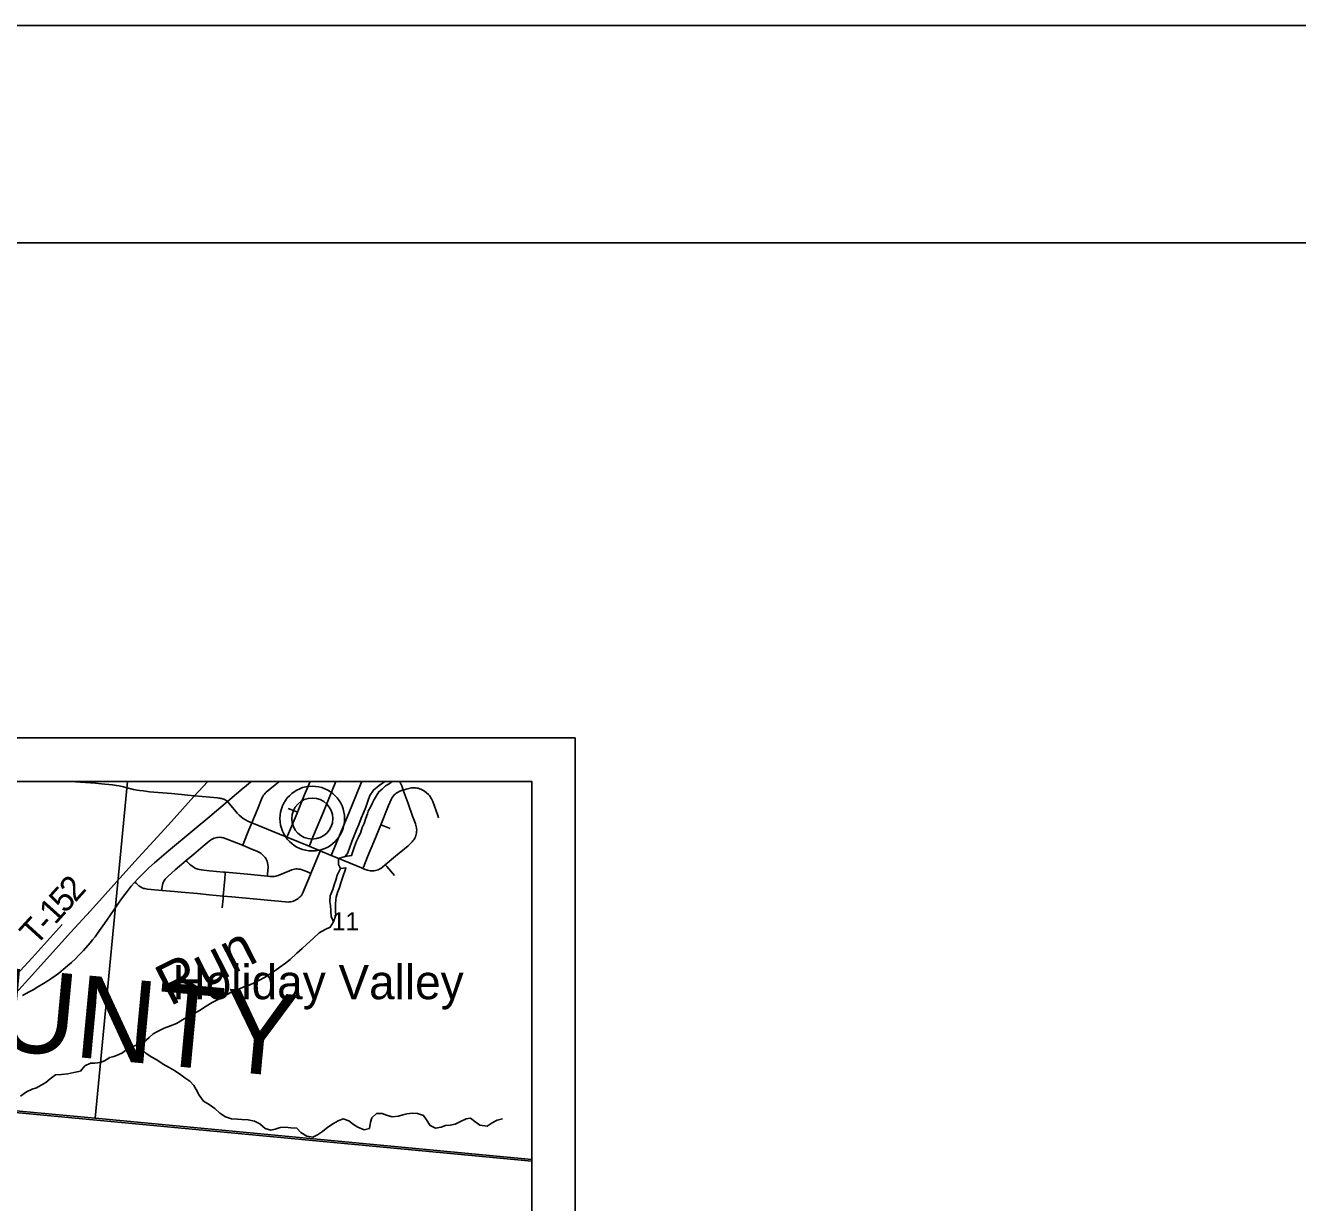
# Model space of a CAD drawing. Extents: x 0 to 34, y 0 to 22.
# Drawn here: x 28.153 to 31.076, y 19.293 to 22 of the extents above; entities that cross this region are included whole.
import ezdxf

# ---------------------------------------------------------------- set-up
doc = ezdxf.new("R2010")
doc.units = 0
for name, color, linetype in [('GM_X_County_Road', 7, 'Continuous'), ('GM_X_County_Text', 7, 'Continuous'), ('GM_X_Minor_Lake', 7, 'Continuous'), ('GM_X_Minor_River', 7, 'Continuous'), ('GM_X_Minor_River_Text', 7, 'Continuous'), ('GM_X_Rail_Line', 7, 'Continuous'), ('GM_X_Section_Text', 7, 'Continuous'), ('GM_X_Township_Road', 7, 'Continuous'), ('GM_X_Township_Road_Text', 7, 'Continuous'), ('GM_X_Unincorporated', 7, 'Continuous'), ('GM_X_Unincorporated_Location', 7, 'Continuous'), ('GM_X_Unincorporated_Text', 7, 'Continuous'), ('SH_Border', 7, 'Continuous'), ('SH_Cut_Line', 7, 'Continuous'), ('SH_Data', 7, 'Continuous')]:
    doc.layers.add(name, color=color, linetype=linetype)

msp = doc.modelspace()

# ---------------------------------------------------------------- linework, layer by layer
at = {"layer": 'GM_X_County_Road'}
for points in [[(28.3874, 20.2618), (27.4198, 20.2618), (27.3522, 19.5759), (28.313, 19.4872)], [(29.3164, 19.3923), (29.3164, 20.2618), (28.3874, 20.2618), (28.313, 19.4872)]]:
    msp.add_lwpolyline(points, close=True, dxfattribs=at)
for points in [[(28.2565, 20.2618), (28.3138, 20.2574), (28.3276, 20.2563), (28.3353, 20.2556), (28.3448, 20.2546), (28.353, 20.2536), (28.3579, 20.2529), (28.3621, 20.2523), (28.3681, 20.2512), (28.3786, 20.2491), (28.3836, 20.248), (28.4014, 20.2434), (28.4057, 20.2425), (28.4091, 20.2419), (28.4154, 20.2408), (28.424, 20.2397), (28.4381, 20.2381), (28.4889, 20.2336), (28.5415, 20.2285), (28.5941, 20.2237), (28.5977, 20.2233), (28.5998, 20.223), (28.602, 20.2227), (28.6032, 20.2224), (28.6042, 20.2222), (28.6052, 20.2219), (28.6069, 20.2213), (28.6088, 20.2206), (28.6116, 20.2195), (28.6141, 20.2181), (28.617, 20.2155)], [(28.617, 20.2155), (28.6535, 20.246), (28.66, 20.2516), (28.6716, 20.2618)], [(28.4041, 20.03), (28.4108, 20.0371), (28.4196, 20.0465), (28.4277, 20.0545), (28.4367, 20.0628), (28.4494, 20.0741), (28.4819, 20.102), (28.5406, 20.151), (28.5764, 20.1808), (28.617, 20.2155)], [(28.1462, 19.7698), (28.1612, 19.7776), (28.1703, 19.7826), (28.1817, 19.7892), (28.1945, 19.797), (28.2044, 19.8032), (28.2138, 19.8095), (28.2287, 19.8203), (28.2399, 19.8292), (28.2497, 19.8374), (28.2585, 19.8453), (28.2681, 19.8541), (28.2757, 19.8618), (28.2863, 19.8728), (28.3019, 19.8906), (28.3073, 19.8973), (28.3129, 19.9047), (28.3177, 19.9111), (28.3401, 19.943), (28.374, 19.9919), (28.3887, 20.0118), (28.396, 20.0208), (28.4026, 20.0284), (28.4041, 20.03)]]:
    msp.add_lwpolyline(points, dxfattribs=at)
at = {"layer": 'GM_X_Minor_Lake'}
for points in [[(28.8875, 20.0893), (28.9025, 20.091), (28.9053, 20.1009), (28.9088, 20.1118), (28.9135, 20.1242), (28.9181, 20.1333), (28.924, 20.1453), (28.9271, 20.1559), (28.9314, 20.1653), (28.9353, 20.177), (28.9388, 20.1872), (28.9404, 20.1933), (28.9458, 20.2023), (28.9505, 20.2121), (28.954, 20.22), (28.9586, 20.2279), (28.9652, 20.238), (28.9724, 20.2436), (28.9805, 20.2515), (28.9888, 20.2563), (28.996, 20.2618)], [(28.8875, 20.0893), (28.8939, 20.0972), (28.8982, 20.1104), (28.9033, 20.1236), (28.9088, 20.1387), (28.9138, 20.1504), (28.9193, 20.1628), (28.9243, 20.1768), (28.9302, 20.1892), (28.9353, 20.2028), (28.94, 20.2164), (28.9447, 20.2292), (28.9527, 20.2416), (28.9657, 20.2524), (28.9791, 20.2617), (28.9792, 20.2618)], [(28.8773, 20.0616), (28.8694, 20.046), (28.8659, 20.0343), (28.8624, 20.0241), (28.8592, 20.0131), (28.853, 19.9988), (28.8524, 19.9859), (28.8542, 19.9764), (28.8544, 19.9643), (28.8554, 19.951), (28.8609, 19.9388)], [(28.8609, 19.9388), (28.866, 19.9543), (28.8658, 19.9627), (28.8655, 19.9725), (28.8656, 19.9801), (28.8665, 19.9892), (28.8673, 19.9952), (28.8701, 20.0066), (28.8748, 20.0179), (28.8779, 20.0284), (28.8807, 20.0375), (28.8838, 20.0466), (28.8873, 20.0556), (28.8893, 20.0632), (28.8773, 20.0616)]]:
    msp.add_lwpolyline(points, dxfattribs=at)
at = {"layer": 'GM_X_Minor_River'}
for points in [[(28.3563, 19.6294), (28.3658, 19.633), (28.3757, 19.6375), (28.3883, 19.6472), (28.4016, 19.6531), (28.4122, 19.6571), (28.4247, 19.6619), (28.437, 19.6727), (28.4465, 19.6813), (28.4583, 19.6876), (28.472, 19.6943), (28.4864, 19.6998), (28.5001, 19.7049), (28.5142, 19.7135), (28.5241, 19.7194), (28.5408, 19.7283), (28.5526, 19.7353), (28.5682, 19.7446), (28.582, 19.7536), (28.5957, 19.7602), (28.6063, 19.7673), (28.6193, 19.7736), (28.6307, 19.7802), (28.6436, 19.7842), (28.6546, 19.789), (28.6671, 19.7934), (28.6782, 19.7986), (28.6896, 19.8038), (28.7025, 19.8108), (28.7132, 19.8179), (28.7261, 19.8261), (28.7376, 19.8343), (28.7505, 19.8439), (28.7612, 19.8525), (28.7765, 19.8664), (28.7891, 19.8776), (28.7991, 19.8869), (28.8147, 19.9011), (28.8277, 19.9135), (28.8414, 19.9209), (28.8536, 19.9268), (28.8609, 19.9388), (28.8554, 19.951), (28.8544, 19.9643), (28.8542, 19.9764), (28.8524, 19.9859), (28.853, 19.9988), (28.8592, 20.0131), (28.8624, 20.0241), (28.8659, 20.0343), (28.8694, 20.046), (28.8773, 20.0616), (28.872, 20.0706), (28.8722, 20.0846), (28.8875, 20.0893), (28.8939, 20.0972), (28.8982, 20.1104), (28.9033, 20.1236), (28.9088, 20.1387), (28.9138, 20.1504), (28.9193, 20.1628), (28.9243, 20.1768), (28.9302, 20.1892), (28.9353, 20.2028), (28.94, 20.2164), (28.9447, 20.2292), (28.9527, 20.2416), (28.9657, 20.2524), (28.9791, 20.2617), (28.9792, 20.2618)], [(28.4087, 19.6558), (28.4178, 19.6483), (28.4297, 19.6368), (28.4421, 19.6283), (28.4552, 19.6217), (28.4691, 19.6113), (28.4834, 19.6036), (28.4939, 19.5981), (28.507, 19.5893), (28.519, 19.5804), (28.531, 19.5723), (28.5399, 19.5627), (28.5455, 19.5532), (28.5525, 19.5402), (28.5622, 19.5264), (28.5753, 19.5187), (28.588, 19.5098), (28.5996, 19.4991), (28.6124, 19.4906), (28.6267, 19.4862), (28.6406, 19.4849), (28.6505, 19.484), (28.6644, 19.4835), (28.6791, 19.4807), (28.6915, 19.4745), (28.7039, 19.4633), (28.7171, 19.4597), (28.7265, 19.4619), (28.7383, 19.4659), (28.7508, 19.4665), (28.7629, 19.4652), (28.7768, 19.4643), (28.7858, 19.4547), (28.7997, 19.4458), (28.8132, 19.4438), (28.8243, 19.4493), (28.8353, 19.4564), (28.8479, 19.4668), (28.8612, 19.475), (28.8719, 19.481), (28.8829, 19.4857), (28.8961, 19.4814), (28.907, 19.4729), (28.9167, 19.4668), (28.931, 19.4609), (28.9435, 19.4638), (28.9456, 19.4778), (28.9487, 19.4883), (28.9598, 19.4984), (28.9727, 19.4979), (28.9828, 19.494), (28.9956, 19.4904), (29.0104, 19.4918), (29.0202, 19.495), (29.0297, 19.4976), (29.0415, 19.499), (29.0543, 19.4984), (29.0678, 19.4933), (29.0749, 19.4838), (29.0827, 19.4704), (29.0955, 19.4646), (29.108, 19.4663), (29.1186, 19.4703), (29.1288, 19.4713), (29.1402, 19.4735), (29.1531, 19.4794), (29.166, 19.486), (29.1759, 19.4874), (29.1856, 19.4797), (29.1972, 19.4709), (29.2138, 19.4692), (29.2256, 19.477), (29.2367, 19.4825), (29.2496, 19.4858)], [(28.1416, 19.538), (28.1557, 19.5481), (28.1683, 19.5544), (28.1781, 19.5573), (28.1892, 19.5636), (28.1998, 19.5691), (28.2101, 19.5781), (28.2223, 19.5867), (28.2356, 19.5876), (28.2507, 19.5894), (28.264, 19.5922), (28.2791, 19.5955), (28.2895, 19.6074), (28.3024, 19.6141), (28.3123, 19.614), (28.3244, 19.6154), (28.3346, 19.6194), (28.3468, 19.6268), (28.3563, 19.6294)]]:
    msp.add_lwpolyline(points, dxfattribs=at)
at = {"layer": 'GM_X_Rail_Line'}
msp.add_lwpolyline([(27.9011, 19.5213), (28.1, 19.7406), (28.1155, 19.7578), (28.16, 19.8071), (28.2576, 19.9148), (28.3022, 19.9642), (28.3365, 20.0019), (28.4044, 20.0773), (28.4814, 20.1618), (28.54, 20.2267), (28.5717, 20.2618)], dxfattribs=at)
at = {"layer": 'GM_X_Township_Road'}
for p, q in [((28.6732, 20.1667), (28.754, 20.1334)), ((28.805, 20.1125), (28.8305, 20.102)), ((28.8305, 20.102), (28.8557, 20.0916))]:
    msp.add_line(p, q, dxfattribs=at)
for points in [[(28.6732, 20.1667), (28.6852, 20.1958), (28.6971, 20.2244), (28.6985, 20.2272), (28.7002, 20.2298), (28.7021, 20.2322), (28.7042, 20.2345), (28.7064, 20.2366), (28.7349, 20.2605), (28.7364, 20.2618)], [(28.7779, 20.191), (28.7934, 20.229), (28.807, 20.2618)], [(28.805, 20.1125), (28.8064, 20.1157), (28.8152, 20.1372), (28.8377, 20.1918), (28.8578, 20.2408), (28.8665, 20.2618)], [(28.8557, 20.0916), (28.857, 20.0948), (28.8961, 20.1888), (28.9231, 20.2547), (28.926, 20.2618)], [(29.0126, 20.2618), (29.0134, 20.2608), (29.0151, 20.2578), (29.0177, 20.2513), (29.0211, 20.2419)], [(28.9697, 20.1622), (28.9875, 20.206), (28.9936, 20.2202), (28.995, 20.223), (28.9966, 20.2257), (28.9984, 20.2282), (29.0005, 20.2305), (29.0027, 20.2326), (29.0052, 20.2346), (29.0078, 20.2362), (29.0133, 20.239), (29.0191, 20.2413), (29.0211, 20.2419)], [(29.0211, 20.2419), (29.028, 20.244), (29.0341, 20.2456), (29.0402, 20.2467), (29.0433, 20.247), (29.0464, 20.247), (29.0495, 20.2468), (29.0526, 20.2464), (29.0556, 20.2458), (29.0586, 20.2448), (29.0615, 20.2437), (29.0643, 20.2424), (29.0697, 20.2394), (29.0747, 20.2357), (29.0793, 20.2315), (29.0814, 20.2292), (29.0832, 20.2268), (29.0849, 20.2241), (29.0864, 20.2214), (29.0889, 20.2157), (29.1003, 20.1835), (29.1025, 20.1777)], [(29.0211, 20.2419), (29.0324, 20.2107), (29.0427, 20.1814), (29.0461, 20.1728), (29.0493, 20.1641), (29.0511, 20.1583), (29.0516, 20.1553), (29.052, 20.1524), (29.0521, 20.1493), (29.052, 20.1463), (29.0516, 20.1433), (29.051, 20.1401), (29.0503, 20.1373), (29.0493, 20.1342)], [(28.617, 20.2155), (28.6336, 20.1963), (28.6398, 20.1887), (28.6439, 20.1843), (28.6485, 20.1802), (28.6534, 20.1765), (28.6586, 20.1733), (28.664, 20.1705), (28.6732, 20.1667)], [(28.754, 20.1334), (28.7554, 20.1367), (28.7771, 20.1889), (28.7779, 20.191)], [(28.7569, 20.1995), (28.773, 20.193), (28.7779, 20.191)], [(28.6519, 20.1149), (28.653, 20.1175), (28.6662, 20.15), (28.6732, 20.1667)], [(28.9284, 20.0616), (28.9296, 20.0646), (28.9393, 20.0881), (28.9535, 20.1226), (28.9697, 20.1622)], [(28.9697, 20.1622), (28.9759, 20.1596), (28.991, 20.1532)], [(28.5224, 20.0795), (28.54, 20.0944), (28.5612, 20.1125), (28.5755, 20.1246), (28.578, 20.1265), (28.5807, 20.1282), (28.5835, 20.1297), (28.5865, 20.1309), (28.5895, 20.1319), (28.5926, 20.1326), (28.5958, 20.1331), (28.599, 20.1333), (28.6022, 20.1331), (28.6053, 20.1326), (28.6084, 20.132), (28.6144, 20.13), (28.6519, 20.1149)], [(28.6519, 20.1149), (28.6692, 20.1078), (28.6864, 20.1006), (28.6892, 20.0992), (28.692, 20.0976), (28.6946, 20.0958), (28.6971, 20.0938), (28.6994, 20.0917), (28.7016, 20.0894), (28.7036, 20.0869), (28.7054, 20.0843), (28.7069, 20.0814), (28.7081, 20.0785), (28.7095, 20.0745), (28.7103, 20.0703), (28.7106, 20.0658), (28.7105, 20.0625), (28.7103, 20.0583), (28.7093, 20.0469), (28.7091, 20.0437)], [(28.754, 20.1334), (28.7558, 20.1327), (28.805, 20.1125)], [(28.9798, 20.0697), (29.0033, 20.0896), (29.0322, 20.1139), (29.0392, 20.1201), (29.0414, 20.1224), (29.0435, 20.1247), (29.0454, 20.1272), (29.0471, 20.1298), (29.048, 20.1315), (29.0493, 20.1342)], [(28.809, 20.0502), (28.8294, 20.0994), (28.8305, 20.102)], [(28.8557, 20.0916), (28.8619, 20.0891), (28.8992, 20.0737), (28.925, 20.063), (28.9284, 20.0616)], [(28.4662, 20.0112), (28.4665, 20.0143), (28.4672, 20.0202), (28.4677, 20.0234), (28.4685, 20.0269), (28.4696, 20.0296), (28.471, 20.0324), (28.4726, 20.0349), (28.4739, 20.0368), (28.4763, 20.0396), (28.4808, 20.044), (28.4973, 20.0583), (28.5224, 20.0795)], [(28.5224, 20.0795), (28.5239, 20.0778), (28.5275, 20.0738), (28.5303, 20.0712), (28.534, 20.068), (28.5373, 20.0657), (28.5416, 20.0632), (28.5448, 20.0617), (28.5488, 20.0602), (28.5529, 20.059), (28.5574, 20.0582), (28.563, 20.0575), (28.5759, 20.0563)], [(28.5759, 20.0563), (28.6078, 20.0532), (28.6124, 20.0528)], [(28.7091, 20.0437), (28.7147, 20.0431), (28.7185, 20.0429), (28.722, 20.0429), (28.725, 20.0432), (28.7281, 20.0437), (28.7306, 20.0445), (28.7334, 20.0456), (28.7597, 20.0564), (28.7655, 20.0586), (28.7685, 20.0594), (28.7715, 20.06), (28.7746, 20.0603), (28.7777, 20.0603), (28.7808, 20.06), (28.7839, 20.0596), (28.7869, 20.0589), (28.7928, 20.0569), (28.8014, 20.0534), (28.809, 20.0502)], [(28.9284, 20.0616), (28.9336, 20.0595), (28.9394, 20.0576), (28.9424, 20.0569), (28.9454, 20.0564), (28.9484, 20.056), (28.9514, 20.056), (28.9544, 20.0563), (28.9573, 20.0568), (28.9602, 20.0576), (28.9632, 20.0585)], [(28.9632, 20.0585), (28.9651, 20.0593), (28.9674, 20.0604), (28.9698, 20.0618), (28.9745, 20.0653), (28.9798, 20.0697)], [(28.9798, 20.0697), (28.9833, 20.0657), (29.001, 20.0451)], [(28.4041, 20.03), (28.407, 20.0275), (28.4137, 20.0218), (28.4161, 20.0199), (28.4188, 20.0182), (28.4215, 20.0169), (28.4244, 20.0158), (28.4274, 20.0151), (28.4336, 20.0142), (28.4662, 20.0112)], [(28.6076, 19.9981), (28.6111, 20.0378), (28.6122, 20.0502), (28.6124, 20.0528)], [(28.6076, 19.9981), (28.6272, 19.9963), (28.7507, 19.9846), (28.7569, 19.9844), (28.76, 19.9846), (28.7631, 19.985), (28.7661, 19.9857), (28.7691, 19.9866), (28.772, 19.9877), (28.7747, 19.9891), (28.7774, 19.9906), (28.7799, 19.9924), (28.7823, 19.9944), (28.7845, 19.9965), (28.7866, 19.9988), (28.7881, 20.0012), (28.7898, 20.0041), (28.7961, 20.0182), (28.808, 20.0475), (28.809, 20.0502)], [(28.6124, 20.0528), (28.6633, 20.0481), (28.7091, 20.0437)], [(28.4662, 20.0112), (28.4954, 20.0086), (28.5109, 20.0072), (28.548, 20.0036), (28.5753, 20.001), (28.6076, 19.9981)], [(28.605, 19.9713), (28.6071, 19.9927), (28.6076, 19.9981)], [(28.0751, 19.755), (28.0836, 19.7642), (28.0932, 19.7748), (28.0984, 19.7808), (28.1036, 19.7865), (28.1079, 19.7911), (28.1113, 19.7947), (28.116, 19.7995), (28.1198, 19.8035), (28.1222, 19.8062), (28.1316, 19.8163), (28.1684, 19.8558), (28.2371, 19.9323)]]:
    msp.add_lwpolyline(points, dxfattribs=at)
at = {"layer": 'GM_X_Unincorporated'}
for radius in [0.0744, 0.0472]:
    msp.add_circle((28.8121, 20.1763), radius, dxfattribs=at)
at = {"layer": 'GM_X_Unincorporated_Location'}
msp.add_line((28.8121, 20.1763), (28.8121, 20.1763), dxfattribs=at)
at = {"layer": 'SH_Border'}
msp.add_lwpolyline([(1.5, 21.5), (33.5, 21.5), (33.5, 0.5), (1.5, 0.5)], close=True, dxfattribs=at)
for points in [[(27.8281, 19.5287), (29.3164, 19.3886), (29.3164, 20.2618), (25.7475, 20.2618)], [(27.8734, 14.472), (28.3712, 14.4228), (28.8639, 14.3656), (28.9072, 14.849), (29.3164, 14.8262), (29.3164, 19.3886), (27.8281, 19.5287)]]:
    msp.add_lwpolyline(points, dxfattribs=at)
at = {"layer": 'SH_Cut_Line'}
msp.add_lwpolyline([(0, 0), (34, 0), (34, 22), (0, 22)], close=True, dxfattribs=at)
at = {"layer": 'SH_Data'}
for p, q in [((22.4164, 20.3618), (29.4164, 20.3618)), ((29.4164, 20.3618), (29.4164, 13.3618)), ((22.5164, 20.2618), (29.3164, 20.2618)), ((29.3164, 20.2618), (29.3164, 13.4618))]:
    msp.add_line(p, q, dxfattribs=at)
msp.add_lwpolyline([(29.3164, 19.3886), (29.3164, 20.2618), (24.3146, 20.2618), (24.3071, 20.185), (24.2795, 19.873), (25.1948, 19.7845), (25.8728, 19.7133), (27.3379, 19.575), (27.4405, 19.5654), (27.4554, 19.5638), (27.4759, 19.5619), (27.4869, 19.5609), (27.6909, 19.5416), (27.8281, 19.5287)], close=True, dxfattribs=at)
msp.add_lwpolyline([(22.5164, 13.4618), (29.3164, 13.4618), (29.3164, 19.3886), (27.8281, 19.5287)], dxfattribs=at)

# ---------------------------------------------------------------- texts
at = {"layer": 'GM_X_County_Text'}
msp.add_text('CLARK COUNTY', height=0.189394, rotation=354.6384, dxfattribs=at).set_placement((26.7909, 19.7667))
at = {"layer": 'GM_X_Minor_River_Text'}
msp.add_text('Run', height=0.09469, rotation=26.9991, dxfattribs=at).set_placement((28.4849, 19.744))
at = {"layer": 'GM_X_Section_Text'}
msp.add_text('11', height=0.04186, rotation=0, dxfattribs=at).set_placement((28.8573, 19.919))
at = {"layer": 'GM_X_Township_Road_Text'}
for s, rotation, p in [('2', 47.9772, (28.2674, 19.982)), ('5', 47.9772, (28.2441, 19.9562)), ('1', 47.9772, (28.2209, 19.9304)), ('T', 47.6962, (28.1766, 19.8816)), ('-', 47.9785, (28.2054, 19.9132))]:
    msp.add_text(s, height=0.0568, rotation=rotation, dxfattribs=at).set_placement(p)
at = {"layer": 'GM_X_Unincorporated_Text'}
msp.add_text('Holiday Valley', height=0.078977, rotation=0, dxfattribs=at).set_placement((28.4908, 19.7609))

doc.saveas('drawing.dxf')
